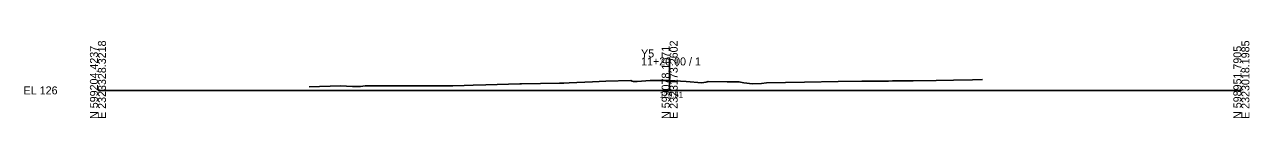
# Model space of a CAD drawing. Extents: x -26 to 4603, y 1490 to 2017.
# Drawn here: x 2774.3 to 3202.8, y 1990.3 to 2017.3 of the extents above; entities that cross this region are included whole.
import ezdxf

# ---------------------------------------------------------------- set-up
doc = ezdxf.new("R2010")
doc.units = 0
for name, color, linetype in [('Exist CMT Pavement', 7, 'Continuous'), ('Exist Cross Section Cell', 7, 'Continuous'), ('Exist XS Center Line Elevation Label', 7, 'Continuous'), ('Exist XS Ground Line', 7, 'Continuous'), ('Prop XS Earthwork Shape', 7, 'Continuous')]:
    doc.layers.add(name, color=color, linetype=linetype)

msp = doc.modelspace()

# ---------------------------------------------------------------- linework, layer by layer
at = {"layer": 'Exist CMT Pavement'}
for points in [[(2999.9, 2003.5), (2999.9, 2003.61), (3000, 2003.61), (3000, 2003.51)], [(3000, 2003.51), (3000, 2003.61), (3000.1, 2003.61), (3000.1, 2003.5)]]:
    msp.add_lwpolyline(points, dxfattribs=at)
at = {"layer": 'Exist Cross Section Cell'}
for p, q in [((3000, 2000), (3000, 2011.55)), ((2800, 2000), (3000, 2000)), ((3000, 2000), (3200, 2000))]:
    msp.add_line(p, q, dxfattribs=at)
at = {"layer": 'Exist XS Ground Line'}
msp.add_lwpolyline([(2873.84, 2001.3), (2884.83, 2001.54), (2889.02, 2001.36), (2890.09, 2001.42), (2891.83, 2001.42), (2893.51, 2001.56), (2924.16, 2001.54), (2928.13, 2001.71), (2931.24, 2001.81), (2935.7, 2001.99), (2947.6, 2002.31), (2948.13, 2002.32), (2961.42, 2002.52), (2962.94, 2002.55), (2964.87, 2002.65), (2972.98, 2003.03), (2977.72, 2003.21), (2986.45, 2003.44), (2986.85, 2003.29), (2987.3, 2003.11), (2987.83, 2003.14), (2988.61, 2003.16), (2993.23, 2003.41), (2999.22, 2003.49), (3000, 2003.51), (3005.79, 2003.06), (3011.27, 2002.66), (3011.92, 2002.74), (3012.69, 2002.85), (3013.07, 2003), (3013.44, 2003.15), (3020.15, 2003.02), (3024.2, 2003.05), (3025.98, 2002.68), (3028.98, 2002.27), (3032.15, 2002.47), (3033.86, 2002.62), (3047.14, 2002.88), (3058.92, 2003.13), (3067.17, 2003.25), (3069.34, 2003.25), (3076.61, 2003.29), (3077.94, 2003.32), (3085.2, 2003.32), (3093.27, 2003.47), (3099.34, 2003.61), (3105.89, 2003.74), (3109.45, 2003.85)], dxfattribs=at)
at = {"layer": 'Prop XS Earthwork Shape'}
for points in [[(2999.9, 2003.61), (3000, 2003.61), (3000, 2003.51), (2999.9, 2003.5)], [(3000, 2003.51), (3000.1, 2003.5), (3000.1, 2003.61), (3000, 2003.61)]]:
    msp.add_lwpolyline(points, close=True, dxfattribs=at)

# ---------------------------------------------------------------- texts
at = {"layer": 'Exist Cross Section Cell'}
for s, p in [('N 599204.4237', (2800, 1990)), ('E 2323328.3218', (2802.8, 1990)), ('N 599078.1071', (3000, 1990)), ('E 2323173.2602', (3002.8, 1990)), ('N 598951.7905', (3200, 1990)), ('E 2323018.1985', (3202.8, 1990))]:
    msp.add_text(s, height=2.8, rotation=90, dxfattribs=at).set_placement(p)
for s, p in [('Y5', (2990, 2011.55)), ('11+20.00 / 1', (2990, 2008.75)), ('EL 126', (2774, 1998.6))]:
    msp.add_text(s, height=2.8, dxfattribs=at).set_placement(p)
at = {"layer": 'Exist XS Center Line Elevation Label'}
msp.add_text('129.51', height=2, dxfattribs=at).set_placement((2996.49, 1997.51))

doc.saveas('drawing.dxf')
